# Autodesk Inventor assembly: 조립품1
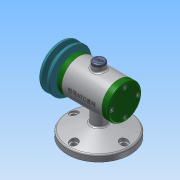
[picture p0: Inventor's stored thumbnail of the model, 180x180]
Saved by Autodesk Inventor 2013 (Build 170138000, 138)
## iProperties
Created: 2018-12
Part Number: 조립품1
Document SubType Name: Assembly
Designer: Administrator
Author: Administrator
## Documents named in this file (15)
- C:\Users\Administrator\Desktop\481207V1038\조립품1.iam
- C:\Users\Administrator\Desktop\481207V1038\본체.ipt
- C:\Users\Administrator\Desktop\481207V1038\베어링 15 x 32 x 9.ipt
- C:\Users\Administrator\Desktop\481207V1038\앞커버.ipt
- C:\Users\Administrator\Desktop\481207V1038\뒤커버.ipt
- C:\Users\Administrator\Desktop\481207V1038\축.ipt
- C:\Users\Administrator\Desktop\481207V1038\오일 실 15 25 7.ipt
- C:\Users\Administrator\Desktop\481207V1038\볼트 M4 x 12.ipt
- C:\Users\Administrator\Desktop\481207V1038\키 3 x 3 x 12.ipt
- C:\Users\Administrator\Desktop\481207V1038\V벨트풀리.ipt
- C:\Users\Administrator\Desktop\481207V1038\와셔 8x17.ipt
- C:\Users\Administrator\Desktop\481207V1038\스프링와셔 8.ipt
- C:\Users\Administrator\Desktop\481207V1038\너트 M8.ipt
- 너트 M8.ipt
- C:\Users\Administrator\Desktop\481207V1038\고무캡.ipt
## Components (2 placed, 2 different names)
1. V벨트풀리:1
2. 고무캡:1
